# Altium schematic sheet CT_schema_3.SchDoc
size 298 x 247 mm
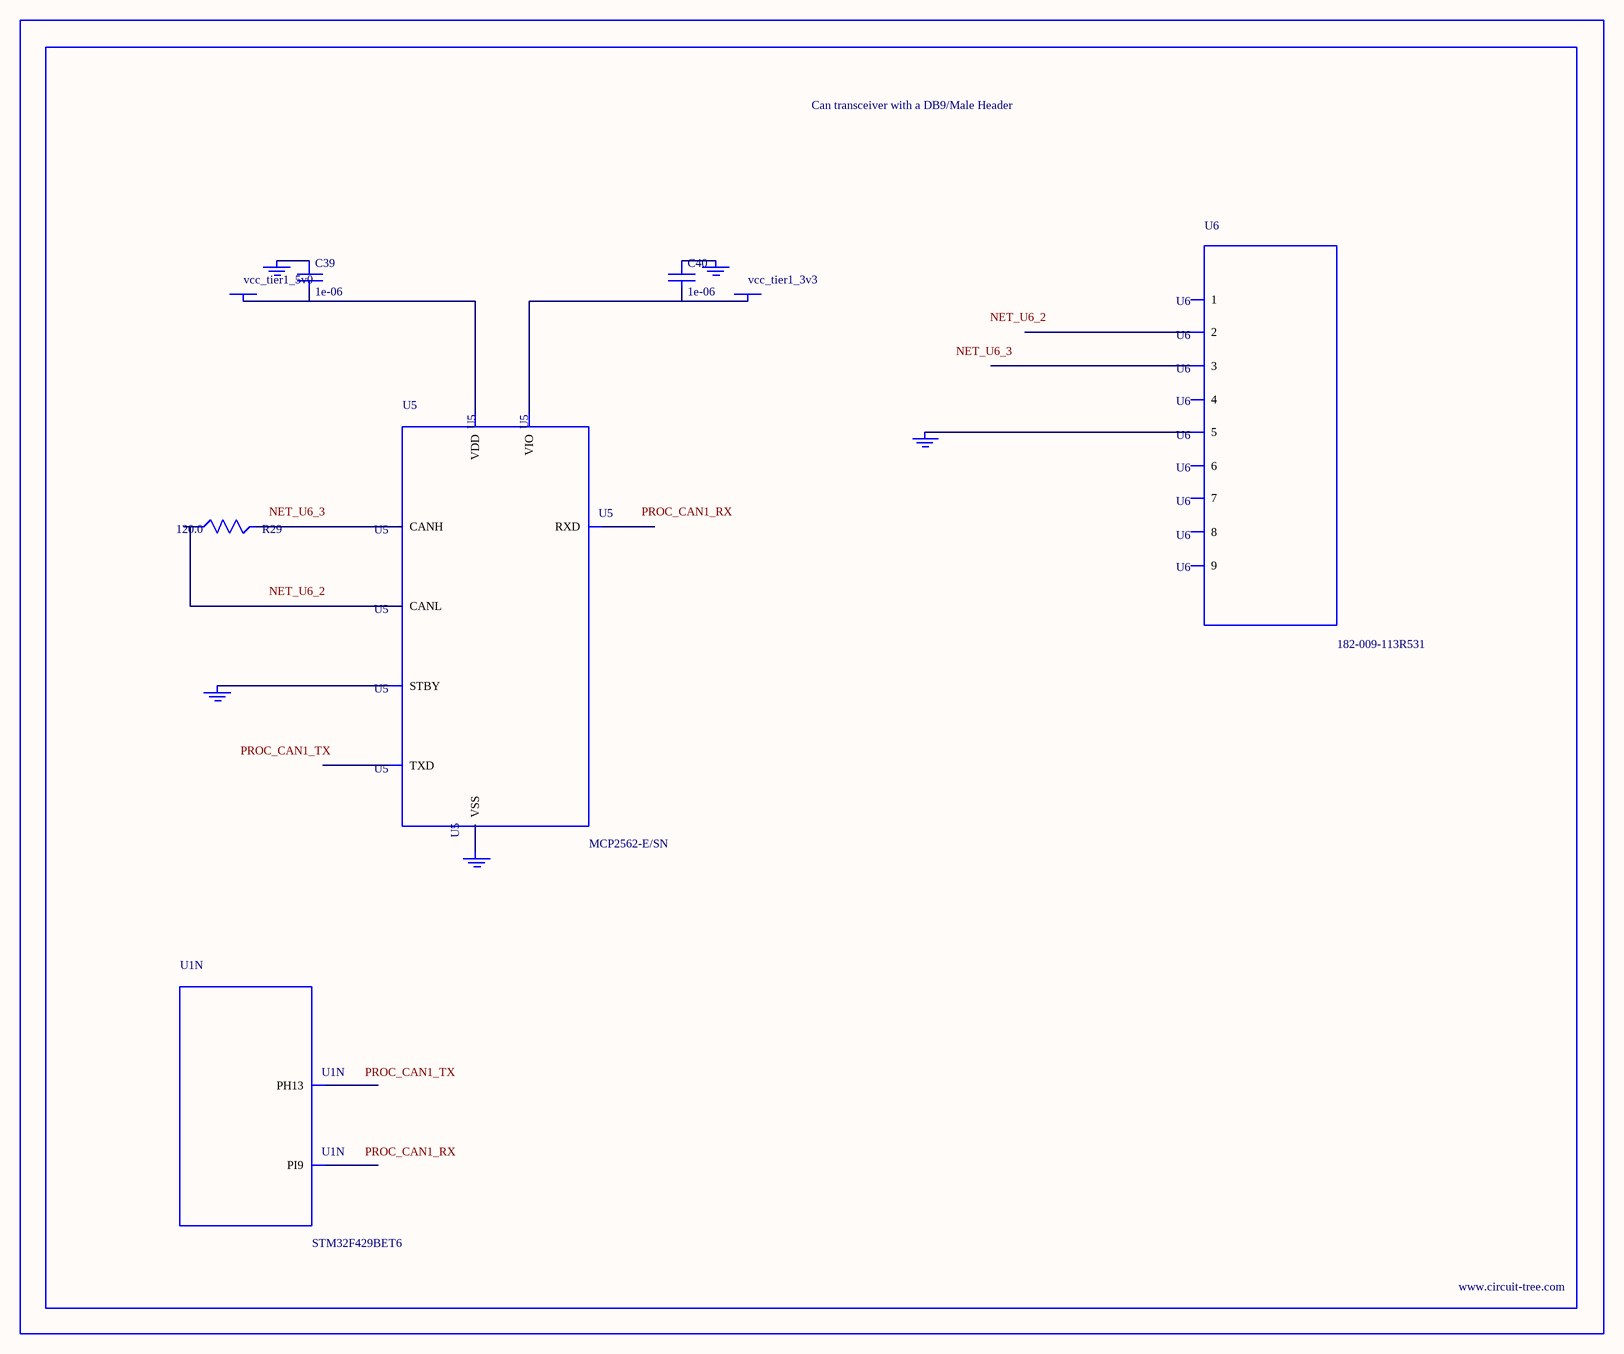
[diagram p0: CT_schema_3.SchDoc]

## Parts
BORDER2  (no value)
C39  1e-06  [C0603]
C40  1e-06  [C0603]
GND_INSTANCE_2_0  (no value)
GND_INSTANCE_2_1  (no value)
GND_INSTANCE_2_2  (no value)
GND_INSTANCE_2_3  (no value)
GND_INSTANCE_2_4  (no value)
POWER_INSTANCE_2_0  vcc_tier1_5v0
POWER_INSTANCE_2_1  vcc_tier1_3v3
R29  120.0  [R0603]
U1  STM32F429BET6  [LQFP208]  (part N of 16)
U5  MCP2562-E/SN  [SOIC-8]
U6  182-009-113R531  [182-009-MALE]

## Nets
NetC39_1: C39.1 GND_INSTANCE_2_0.0(GND)
NetC39_2: C39.2 POWER_INSTANCE_2_0.0(PWR) U5.3(VDD)
NetC40_1: C40.1 GND_INSTANCE_2_1.0(GND)
NetC40_2: C40.2 POWER_INSTANCE_2_1.0(PWR) U5.5(VIO)
NetGND_INSTANCE_2_2_0: GND_INSTANCE_2_2.0(GND) U5.8(STBY)
NetGND_INSTANCE_2_3_0: GND_INSTANCE_2_3.0(GND) U5.2(VSS)
NetGND_INSTANCE_2_4_0: GND_INSTANCE_2_4.0(GND) U6.5
NetR29_1: R29.1 U5.6(CANL)
NetR29_2: R29.2 U5.7(CANH)

Not connected (* = marked no-connect by the designer): U1 11(PI9) 151(PH13); U5 1(TXD) 4(RXD); U6 1 2 3 4 6 7 8 9

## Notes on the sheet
- Labels drawn without touching a wire or pin: NET_U6_2, NET_U6_3, PROC_CAN1_RX, PROC_CAN1_TX

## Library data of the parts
BORDER2 = BORDER_PAGE2
C39 C40 = C0603C105K3RACTU
GND_INSTANCE_2_0-GND_INSTANCE_2_4 = GND
POWER_INSTANCE_2_0 POWER_INSTANCE_2_1 = PWR
R29 = RC0603JR-07120RL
